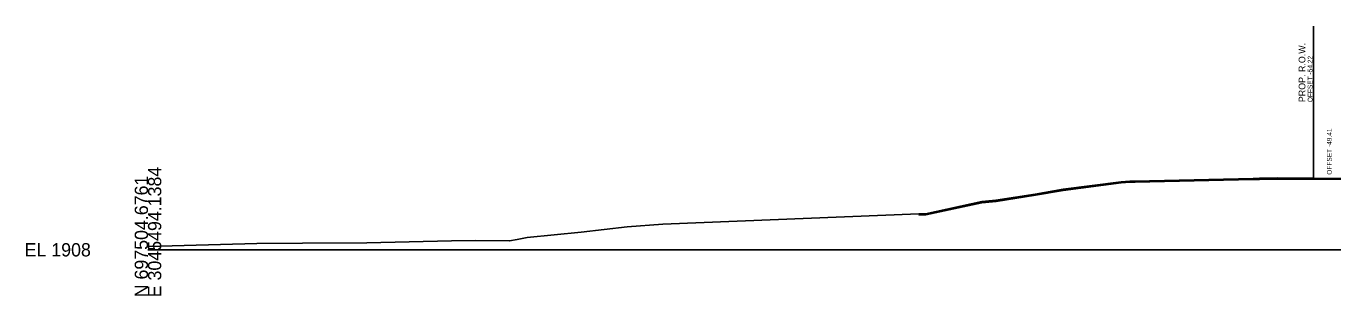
# Model space of a CAD drawing. Extents: x 1574 to 14903, y 7971 to 16537.
# Drawn here: x 14274.3 to 14549.8, y 9490.3 to 9547.1 of the extents above; entities that cross this region are included whole.
import ezdxf

# ---------------------------------------------------------------- set-up
doc = ezdxf.new("R2010")
doc.units = 0
for name, color, linetype in [('DESIGN - ROW - Right-of-Way and Easement Labels', 7, 'Continuous'), ('DESIGN - ROW - Right-of-Way Linework', 7, 'Continuous'), ('DESIGN - SHEET - Light Grid', 7, 'Continuous'), ('DESIGN - TYPICAL - Slope Tie Text', 7, 'Continuous'), ('SURVEY - GROUND - Bottom of Topsoil Layer', 7, 'Continuous'), ('SURVEY - GROUND - Top of Ground', 7, 'Continuous')]:
    doc.layers.add(name, color=color, linetype=linetype)

msp = doc.modelspace()

# ---------------------------------------------------------------- linework, layer by layer
at = {"layer": 'DESIGN - ROW - Right-of-Way Linework'}
msp.add_line((14545.78, 9515.08), (14545.78, 9547.08), dxfattribs=at)
at = {"layer": 'DESIGN - SHEET - Light Grid'}
msp.add_line((14300, 9500), (14600, 9500), dxfattribs=at)
at = {"layer": 'SURVEY - GROUND - Bottom of Topsoil Layer'}
msp.add_lwpolyline([(14462.56, 9507.3), (14463.98, 9507.35), (14475.85, 9509.9), (14478.83, 9510.18), (14487.11, 9511.47), (14493, 9512.49), (14505.19, 9514.09), (14507.06, 9514.22), (14507.66, 9514.23), (14508.12, 9514.23), (14533.01, 9514.78), (14534.37, 9514.81), (14538.12, 9514.89), (14553.59, 9514.78), (14556.91, 9513.72), (14560.02, 9513.57), (14562.88, 9513.34), (14564.67, 9513.04), (14570.99, 9512.02), (14573.1, 9511.35), (14574.51, 9511.13), (14576.43, 9510.88), (14578.72, 9510.19)], dxfattribs=at)
at = {"layer": 'SURVEY - GROUND - Top of Ground'}
msp.add_line((14408.53, 9505.36), (14462.55, 9507.55), dxfattribs=at)
msp.add_line((14408.53, 9505.36), (14462.55, 9507.55), dxfattribs=at)
for points in [[(14462.55, 9507.55), (14463.95, 9507.6), (14475.81, 9510.15), (14478.8, 9510.43), (14487.07, 9511.71), (14492.96, 9512.74), (14505.17, 9514.34), (14507.05, 9514.47), (14507.66, 9514.48), (14508.11, 9514.48), (14533.01, 9515.03), (14534.37, 9515.06), (14538.12, 9515.14), (14553.63, 9515.03)], [(14462.55, 9507.55), (14463.95, 9507.6), (14475.81, 9510.15), (14478.8, 9510.43), (14487.07, 9511.71), (14492.96, 9512.74), (14505.17, 9514.34), (14507.05, 9514.47), (14507.66, 9514.48), (14508.11, 9514.48), (14533.01, 9515.03), (14534.37, 9515.06), (14538.12, 9515.14), (14553.63, 9515.03)], [(14300, 9500.72), (14322.95, 9501.29), (14332.6, 9501.4), (14346.17, 9501.43), (14364.01, 9501.89), (14369.05, 9501.93), (14376.25, 9501.88), (14377.85, 9502.19), (14379.96, 9502.59), (14391.34, 9503.69), (14401.05, 9504.8), (14408.53, 9505.36)], [(14300, 9500.72), (14322.95, 9501.29), (14332.6, 9501.4), (14346.17, 9501.43), (14364.01, 9501.89), (14369.05, 9501.93), (14376.25, 9501.88), (14377.85, 9502.19), (14379.96, 9502.59), (14391.34, 9503.69), (14401.05, 9504.8), (14408.53, 9505.36)]]:
    msp.add_lwpolyline(points, dxfattribs=at)

# ---------------------------------------------------------------- texts
at = {"layer": 'DESIGN - ROW - Right-of-Way and Easement Labels'}
for s, height, p in [('PROP. R.O.W.', 1.4, (14544.03, 9531.08)), ('OFFSET -54.22', 1, (14545.53, 9531.08))]:
    msp.add_text(s, height=height, rotation=90, dxfattribs=at).set_placement(p)
at = {"layer": 'DESIGN - SHEET - Light Grid'}
for s, p in [('E 3045494.1384', (14302.8, 9490)), ('N 697504.6761', (14300, 9490))]:
    msp.add_text(s, height=2.8, rotation=90, dxfattribs=at).set_placement(p)
msp.add_text('EL 1908', height=2.8, dxfattribs=at).set_placement((14274, 9498.6))
at = {"layer": 'DESIGN - TYPICAL - Slope Tie Text'}
msp.add_text('OFFSET -49.41', height=1, rotation=90, dxfattribs=at).set_placement((14549.59, 9515.8))

doc.saveas('drawing.dxf')
